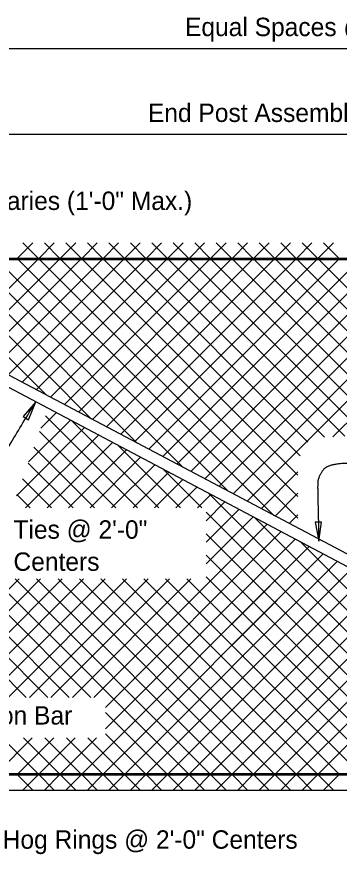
# Model space of a CAD drawing. Extents: x 0.2 to 40.8, y 0.5 to 25.7.
# Drawn here: x 6.74 to 10.28, y 16.52 to 25.7 of the extents above; entities that cross this region are included whole.
import ezdxf

# ---------------------------------------------------------------- set-up
doc = ezdxf.new("R2010")
doc.units = 0
for name, color, linetype in [('Dimension', 7, 'Continuous'), ('Miscellaneous', 7, 'Continuous'), ('SteelMisc', 7, 'Continuous'), ('SupstrConc', 7, 'Continuous'), ('TextStructures', 7, 'Continuous')]:
    doc.layers.add(name, color=color, linetype=linetype)

msp = doc.modelspace()

# ---------------------------------------------------------------- linework, layer by layer
at = {"layer": 'Dimension'}
for p, q in [((0.2352, 25.3556), (13.615, 25.3556)), ((4.615, 24.4146), (14.615, 24.4146))]:
    msp.add_line(p, q, dxfattribs=at)
for points in [[(6.945, 21.4806), (6.8059, 21.3216), (6.8661, 21.2847)], [(10.0503, 19.9529), (10.0815, 20.1618), (10.011, 20.1604)]]:
    msp.add_lwpolyline(points, close=True, dxfattribs=at)
for points in [[(6.6174, 20.081), (6.4865, 20.0669), (6.3036, 20.1341), (6.3121, 20.4608), (6.945, 21.4806)], [(10.4281, 20.8052), (10.1586, 20.8133), (10.0405, 20.6549), (10.0376, 20.5337), (10.0422, 20.3659), (10.0503, 19.9529)]]:
    msp.add_open_spline(points, degree=2, dxfattribs=at)
at = {"layer": 'Miscellaneous'}
for p, q in [((6.745, 23.0578), (6.9116, 23.2245)), ((6.8042, 23.2245), (6.9709, 23.0578)), ((6.9807, 23.0578), (7.1473, 23.2245)), ((7.0399, 23.2245), (7.2066, 23.0578)), ((7.2164, 23.0578), (7.383, 23.2245)), ((7.2756, 23.2245), (7.4423, 23.0578)), ((7.4521, 23.0578), (7.6187, 23.2245)), ((7.5113, 23.2245), (7.678, 23.0578)), ((7.6878, 23.0578), (7.8544, 23.2245)), ((7.747, 23.2245), (7.9137, 23.0578)), ((7.9235, 23.0578), (8.0901, 23.2245)), ((7.9827, 23.2245), (8.1494, 23.0578)), ((8.1592, 23.0578), (8.3258, 23.2245)), ((8.2184, 23.2245), (8.3851, 23.0578)), ((8.3949, 23.0578), (8.5615, 23.2245)), ((8.4541, 23.2245), (8.6208, 23.0578)), ((8.6306, 23.0578), (8.7972, 23.2245)), ((8.6898, 23.2245), (8.8565, 23.0578)), ((8.8663, 23.0578), (9.0329, 23.2245)), ((8.9255, 23.2245), (9.0922, 23.0578)), ((9.102, 23.0578), (9.2687, 23.2245)), ((9.1612, 23.2245), (9.3279, 23.0578)), ((9.3377, 23.0578), (9.5044, 23.2245)), ((9.3969, 23.2245), (9.5636, 23.0578)), ((9.5734, 23.0578), (9.7401, 23.2245)), ((9.6326, 23.2245), (9.7993, 23.0578)), ((9.8091, 23.0578), (9.9758, 23.2245)), ((9.8683, 23.2245), (10.035, 23.0578)), ((10.0448, 23.0578), (10.2115, 23.2245)), ((10.104, 23.2245), (10.2707, 23.0578)), ((5.8071, 23.0431), (7.5577, 21.2925)), ((6.0252, 22.1023), (6.9659, 23.0431)), ((6.0428, 23.0431), (8.0575, 21.0283)), ((6.1794, 22.0209), (7.2016, 23.0431)), ((6.2785, 23.0431), (8.5574, 20.7642)), ((6.3336, 21.9394), (7.4373, 23.0431)), ((6.4878, 21.8579), (7.673, 23.0431)), ((6.5142, 23.0431), (9.0572, 20.5)), ((6.642, 21.7764), (7.9087, 23.0431)), ((6.7499, 23.0431), (9.5571, 20.2359)), ((6.7962, 21.6949), (8.1444, 23.0431)), ((6.9504, 21.6134), (8.3801, 23.0431)), ((6.9856, 23.0431), (9.8224, 20.2063)), ((7.1046, 21.5319), (8.6158, 23.0431)), ((7.2213, 23.0431), (9.8224, 20.442)), ((7.2589, 21.4504), (8.8515, 23.0431)), ((7.4131, 21.3689), (9.0872, 23.0431)), ((7.457, 23.0431), (9.8224, 20.6777)), ((7.5673, 21.2874), (9.3229, 23.0431)), ((7.6927, 23.0431), (9.8467, 20.8891)), ((7.7215, 21.2059), (9.5586, 23.0431)), ((7.8757, 21.1244), (9.7943, 23.0431)), ((7.9284, 23.0431), (9.9312, 21.0403)), ((8.0299, 21.0429), (10.03, 23.0431)), ((8.1641, 23.0431), (10.1124, 21.0948)), ((8.1841, 20.9614), (10.2657, 23.0431)), ((8.3383, 20.88), (10.5014, 23.0431)), ((8.3998, 23.0431), (10.3365, 21.1064)), ((8.4925, 20.7985), (10.7372, 23.0431)), ((8.6355, 23.0431), (10.5722, 21.1064)), ((8.6467, 20.717), (10.9729, 23.0431)), ((8.8009, 20.6355), (11.2086, 23.0431)), ((8.8712, 23.0431), (10.8079, 21.1064)), ((8.9552, 20.554), (11.4443, 23.0431)), ((9.1069, 23.0431), (11.0436, 21.1064)), ((9.1094, 20.4725), (11.68, 23.0431)), ((9.2636, 20.391), (11.9157, 23.0431)), ((9.3426, 23.0431), (11.2793, 21.1064)), ((9.5783, 23.0431), (11.515, 21.1064)), ((9.814, 23.0431), (11.7507, 21.1064)), ((10.0497, 23.0431), (11.9864, 21.1064)), ((10.2043, 21.096), (12.1514, 23.0431)), ((5.7518, 22.8627), (7.0578, 21.5566)), ((7.0006, 21.1922), (7.1701, 21.3617)), ((7.0502, 21.3286), (8.0609, 20.3178)), ((6.8661, 20.822), (7.3243, 21.2802)), ((7.3455, 21.269), (8.2966, 20.3178)), ((4.8859, 21.1359), (8.6158, 17.4059)), ((6.7317, 20.4518), (7.4785, 21.1987)), ((6.8334, 20.3178), (7.6327, 21.1172)), ((6.9874, 21.1557), (7.8252, 20.3178)), ((7.0691, 20.3178), (7.7869, 21.0357)), ((6.9246, 20.9828), (7.5895, 20.3178)), ((7.3048, 20.3178), (7.9412, 20.9542)), ((7.8453, 21.0048), (8.5323, 20.3178)), ((4.8859, 20.9002), (7.5472, 18.2388)), ((7.5405, 20.3178), (8.0954, 20.8727)), ((6.8618, 20.8099), (7.3538, 20.3178)), ((7.7762, 20.3178), (8.2496, 20.7912)), ((4.8859, 20.6644), (7.3115, 18.2388)), ((8.0119, 20.3178), (8.4038, 20.7097)), ((8.3452, 20.7407), (8.768, 20.3178)), ((9.4178, 20.3095), (9.8224, 20.7141)), ((6.7989, 20.637), (7.1181, 20.3178)), ((8.2476, 20.3178), (8.558, 20.6282)), ((8.4833, 20.3178), (8.7122, 20.5467)), ((8.845, 20.4766), (11.9157, 17.4059)), ((9.572, 20.228), (9.8224, 20.4784)), ((4.8859, 20.4287), (7.0758, 18.2388)), ((6.7361, 20.4641), (6.8824, 20.3178)), ((8.719, 20.3178), (8.8664, 20.4652)), ((8.8145, 20.1777), (9.0206, 20.3838)), ((8.8145, 19.942), (9.1748, 20.3023)), ((8.8145, 20.2713), (11.68, 17.4059)), ((8.8145, 19.7063), (9.3291, 20.2208)), ((9.3449, 20.2124), (12.1514, 17.4059)), ((9.7262, 20.1465), (9.8224, 20.2427)), ((4.8876, 20.1913), (6.8401, 18.2388)), ((7.5828, 18.2388), (9.4833, 20.1393)), ((7.7103, 18.1306), (9.6375, 20.0578)), ((8.8145, 20.0356), (11.4443, 17.4059)), ((7.7103, 17.8949), (9.7917, 19.9763)), ((9.0917, 19.2763), (9.7917, 19.9763)), ((9.8447, 19.9483), (12.3871, 17.4059)), ((7.457, 17.4059), (9.9459, 19.8948)), ((9.0917, 19.0406), (9.9459, 19.8948)), ((7.6927, 17.4059), (10.1001, 19.8133)), ((8.8145, 19.7999), (11.2086, 17.4059)), ((9.0917, 18.8049), (10.1001, 19.8133)), ((7.9284, 17.4059), (10.2543, 19.7318)), ((8.1641, 17.4059), (10.4085, 19.6503)), ((8.3998, 17.4059), (10.5627, 19.5688)), ((8.8145, 19.5642), (10.9729, 17.4059)), ((5.7273, 18.5047), (6.7626, 19.54)), ((5.8187, 18.3603), (6.9983, 19.54)), ((5.9329, 18.2388), (7.234, 19.54)), ((6.1686, 18.2388), (7.4697, 19.54)), ((6.4043, 18.2388), (7.7055, 19.54)), ((6.64, 18.2388), (7.9412, 19.54)), ((6.7175, 19.54), (8.8515, 17.4059)), ((6.8757, 18.2388), (8.1769, 19.54)), ((6.9532, 19.54), (9.0872, 17.4059)), ((7.1114, 18.2388), (8.4126, 19.54)), ((7.1889, 19.54), (9.3229, 17.4059)), ((7.3471, 18.2388), (8.6483, 19.54)), ((7.4246, 19.54), (9.5586, 17.4059)), ((7.6603, 19.54), (9.7943, 17.4059)), ((7.896, 19.54), (10.03, 17.4059)), ((8.1317, 19.54), (10.2657, 17.4059)), ((8.3674, 19.54), (10.5014, 17.4059)), ((8.6031, 19.54), (10.7372, 17.4059)), ((8.6355, 17.4059), (10.717, 19.4873)), ((8.8712, 17.4059), (10.8712, 19.4059)), ((9.1069, 17.4059), (11.0254, 19.3244)), ((9.3426, 17.4059), (11.1796, 19.2429)), ((9.5783, 17.4059), (11.3338, 19.1614)), ((9.814, 17.4059), (11.488, 19.0799)), ((10.0497, 17.4059), (11.6422, 18.9984)), ((7.7103, 18.0757), (8.3801, 17.4059)), ((7.7103, 17.84), (8.1444, 17.4059)), ((6.5142, 17.4059), (6.9059, 17.7976)), ((6.5742, 17.7976), (6.9659, 17.4059)), ((6.7499, 17.4059), (7.1416, 17.7976)), ((6.8099, 17.7976), (7.2016, 17.4059)), ((6.9856, 17.4059), (7.3773, 17.7976)), ((7.0456, 17.7976), (7.4373, 17.4059)), ((7.2213, 17.4059), (7.613, 17.7976)), ((7.2813, 17.7976), (7.673, 17.4059)), ((7.517, 17.7976), (7.9087, 17.4059)), ((6.745, 17.3912), (6.9116, 17.2245)), ((6.8042, 17.2245), (6.9709, 17.3912)), ((6.9807, 17.3912), (7.1473, 17.2245)), ((7.0399, 17.2245), (7.2066, 17.3912)), ((7.2164, 17.3912), (7.383, 17.2245)), ((7.2756, 17.2245), (7.4423, 17.3912)), ((7.4521, 17.3912), (7.6187, 17.2245)), ((7.5113, 17.2245), (7.678, 17.3912)), ((7.6878, 17.3912), (7.8544, 17.2245)), ((7.747, 17.2245), (7.9137, 17.3912)), ((7.9235, 17.3912), (8.0901, 17.2245)), ((7.9827, 17.2245), (8.1494, 17.3912)), ((8.1592, 17.3912), (8.3258, 17.2245)), ((8.2184, 17.2245), (8.3851, 17.3912)), ((8.3949, 17.3912), (8.5615, 17.2245)), ((8.4541, 17.2245), (8.6208, 17.3912)), ((8.6306, 17.3912), (8.7972, 17.2245)), ((8.6898, 17.2245), (8.8565, 17.3912)), ((8.8663, 17.3912), (9.0329, 17.2245)), ((8.9255, 17.2245), (9.0922, 17.3912)), ((9.102, 17.3912), (9.2687, 17.2245)), ((9.1612, 17.2245), (9.3279, 17.3912)), ((9.3377, 17.3912), (9.5044, 17.2245)), ((9.3969, 17.2245), (9.5636, 17.3912)), ((9.5734, 17.3912), (9.7401, 17.2245)), ((9.6326, 17.2245), (9.7993, 17.3912)), ((9.8091, 17.3912), (9.9758, 17.2245)), ((9.8683, 17.2245), (10.035, 17.3912)), ((10.0448, 17.3912), (10.2115, 17.2245)), ((10.104, 17.2245), (10.2707, 17.3912))]:
    msp.add_line(p, q, dxfattribs=at)
at = {"layer": 'SteelMisc'}
for p, q in [((5.8052, 23.0578), (14.2941, 23.0578)), ((5.8052, 23.0431), (14.3207, 23.0431)), ((14.2677, 17.7466), (5.0181, 22.6346)), ((14.2117, 17.6406), (4.962, 22.5285)), ((4.923, 17.3912), (14.3207, 17.3912)), ((4.9243, 17.4059), (14.2941, 17.4059))]:
    msp.add_line(p, q, dxfattribs=at)
at = {"layer": 'SupstrConc'}
msp.add_line((4.7609, 17.2245), (11.2293, 17.2245), dxfattribs=at)

# ---------------------------------------------------------------- texts
at = {"layer": 'Dimension'}
for s, p in [('Ties @ 2\'-0" ', (6.6999, 19.9805)), ('Centers', (6.6999, 19.6285))]:
    msp.add_text(s, height=0.2016, dxfattribs=at).set_placement(p)
at = {"layer": 'TextStructures'}
for s, p in [('Equal Spaces @ 10\'-0" Max. (Posts may be shifted minimally to meet required clearances)', (8.5826, 25.4902)), ('End Post Assembly', (8.1753, 24.5492)), ('Varies (1\'-0" Max.)', (6.4474, 23.5846)), ('Tension Bar', (5.892, 17.9432)), ('Hog Rings @ 2\'-0" Centers', (6.5816, 16.5823))]:
    msp.add_text(s, height=0.2016, dxfattribs=at).set_placement(p)

doc.saveas('drawing.dxf')
